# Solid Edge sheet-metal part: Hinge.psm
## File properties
Author: m_hel
Template: iso metric sheet metal.psm
Last saved by: m_hel
Revision: 16
Application: Solid Edge
Accuracy: 0,990
Material Thickness: 3,00 mm
Bend Radius: 1,00 mm
Relief Width: 1,00 mm
Relief Length: 0,00 mm
Neutral Factor: 0,330
Minimum Arc Length: 0,10 mm
Deviational Tolerance: 0,10 mm
Username: m_hel
Material: Chrome
Face Style: Chrome
Fill Style: Normal
Virtual Style: Normal
Grouping: Uncategorized
LibraryName: Custom Materials
Coef. of Thermal Exp: 0.0
Thermal Conductivity: 0.0
Specific Heat: 0.0
Modulus of Elasticity: 0.0
Poisson's Ratio: 0.0
Yield Stress: 0.0
Ultimate Stress: 0.0
Elongation: 0.0
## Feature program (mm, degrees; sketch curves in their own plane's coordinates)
base contour flange "ContourFlange_1"
sketch for "unnamed Cutout 1" plane through (0, -26.5311, 3) normal (0, 0, 1) x-axis (1, 0, 0)
  line (-24.5861, 21.1216) -> (-17.015, -21.8162)
  arc centre (-15.0454, -21.4689) radius 2 from (-17.015, -21.8162) to (-15.0454, -23.4689) ccw
  line (-15.0454, -23.4689) -> (15.0454, -23.4689)
  arc centre (15.0454, -21.4689) radius 2 from (15.0454, -23.4689) to (17.015, -21.8162) ccw
  line (17.015, -21.8162) -> (24.5861, 21.1216)
  arc centre (22.6165, 21.4689) radius 2 from (24.5861, 21.1216) to (22.6165, 23.4689) ccw
  line (22.6165, 23.4689) -> (20, 23.4689)
  line (20, 23.4689) -> (20, 39.5311)
  line (20, 39.5311) -> (0, 39.5311)
  line (0, 39.5311) -> (0, 23.4689)
  line (0, 23.4689) -> (-22.6165, 23.4689)
  arc centre (-22.6165, 21.4689) radius 2 from (-24.5861, 21.1216) to (-22.6165, 23.4689) cw
extrude "unnamed Cutout 1" cut
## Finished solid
Body 1: solid body, 18 faces, 44 edges, 28 vertices.
  Faces by surface: plane 10, cylinder 8
  Edges by curve: line 28, circle 16
Bounding box of the edges (mm): 49.233 x 63.000 x 16.000, from (-24.6165, -50, -8) to (24.6165, 13, 8).
Cylindrical faces by radius (mm): R1 x1, R2 x4, R4 x1, R5 x1, R8 x1
Planar faces by outward normal: +x 1, +y 2, +z 1, -x 1, -y 1, -z 1, oblique 3
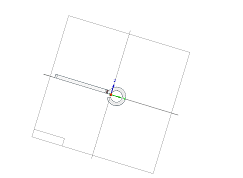
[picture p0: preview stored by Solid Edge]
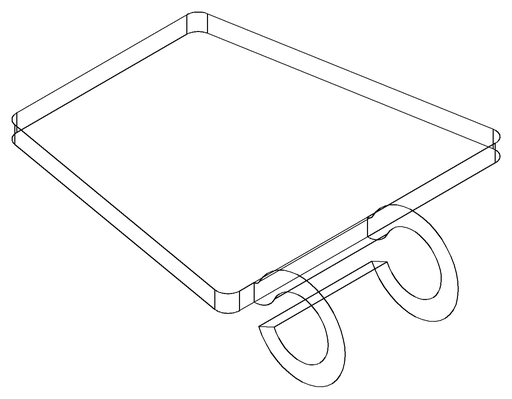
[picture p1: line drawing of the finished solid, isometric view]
